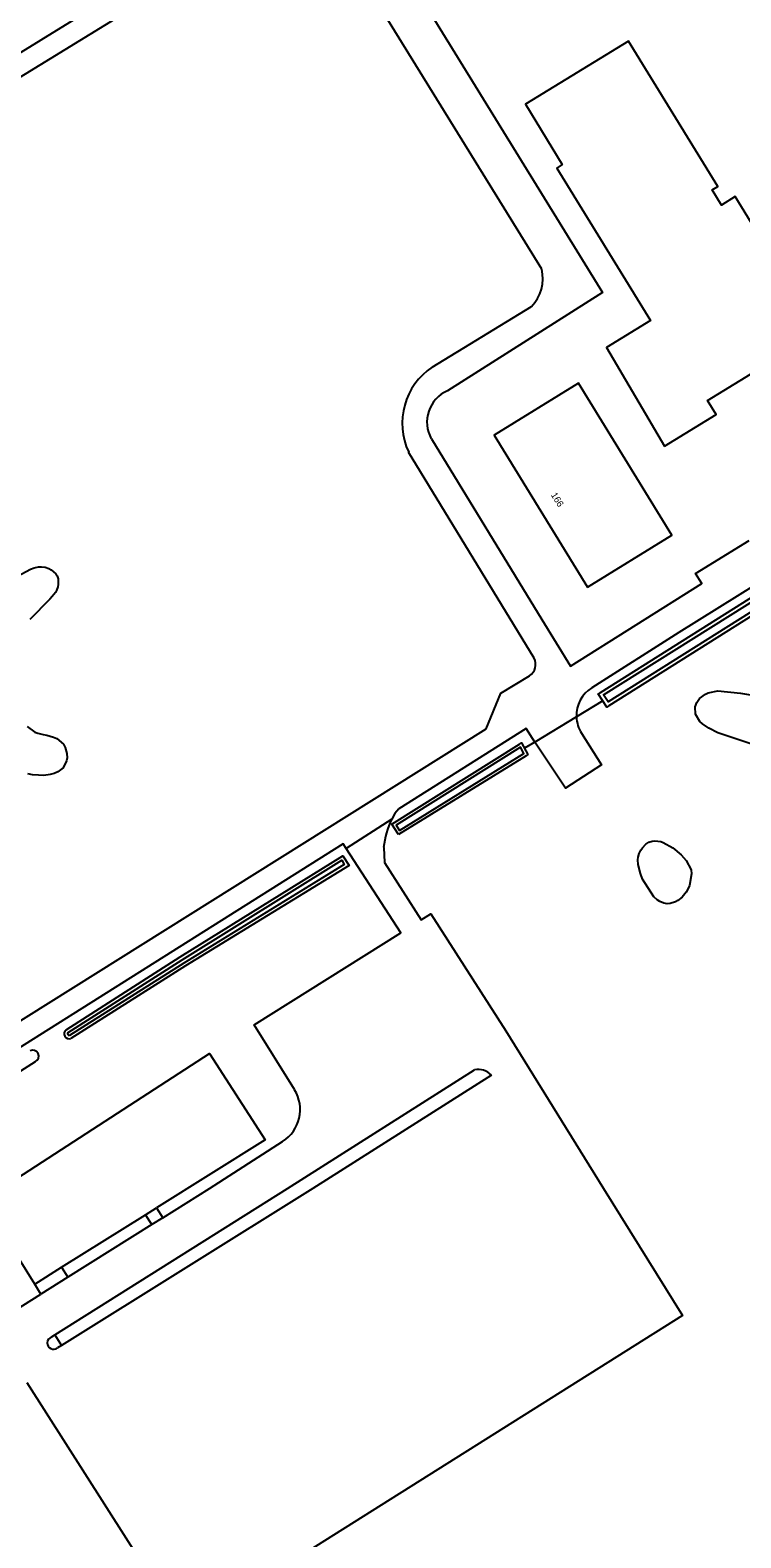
# Model space of a CAD drawing. Extents: x 156061 to 157804, y 383451 to 385640.
# Drawn here: x 157382.9 to 157488.8, y 384198 to 384422.5 of the extents above; entities that cross this region are included whole.
import ezdxf

# ---------------------------------------------------------------- set-up
doc = ezdxf.new("R2010")
doc.units = 0
for name, color, linetype in [('IMGEO_Duiker', 7, 'Continuous'), ('IMGEO_Groenvoorziening', 7, 'Continuous'), ('IMGEO_Pand', 7, 'Continuous'), ('IMGEO_Pand_nummerreeks', 7, 'Continuous'), ('IMGEO_Parkeervlak_open', 7, 'Continuous'), ('IMGEO_Rijbaan_lokaal_open', 7, 'Continuous'), ('IMGEO_Verkeerseiland_gesloten', 7, 'Continuous'), ('IMGEO_Voetpad_gesloten', 7, 'Continuous'), ('IMGEO_Voetpad_open', 7, 'Continuous'), ('IMGEO_Waterloop', 7, 'Continuous')]:
    doc.layers.add(name, color=color, linetype=linetype)

msp = doc.modelspace()

# ---------------------------------------------------------------- linework, layer by layer
at = {"layer": 'IMGEO_Duiker'}
msp.add_lwpolyline([(157468.24, 384322.62), (157464.32, 384320.24), (157458.11, 384316.49), (157456.56, 384315.56)], dxfattribs=at)
at = {"layer": 'IMGEO_Groenvoorziening'}
for points in [[(157500, 384341.28), (157469.14, 384321.89), (157468.85, 384321.71), (157467.54, 384323.67), (157467.87, 384323.89), (157500, 384344.09), (157567.48, 384386.23), (157568.22, 384386.06), (157568.84, 384385.18), (157568.87, 384384.42), (157500, 384341.28)], [(157375.35, 384338.18), (157382.95, 384342.26), (157383.48, 384342.45), (157384.14, 384342.61), (157384.56, 384342.61), (157385.11, 384342.52), (157385.65, 384342.33), (157386.01, 384342.15), (157386.7, 384341.57), (157386.9, 384341.26), (157387.05, 384340.81), (157387.06, 384339.96), (157387, 384339.62), (157386.82, 384339.09), (157386.64, 384338.76), (157386.19, 384338.19), (157385.8, 384337.79), (157382.85, 384334.74)], [(157490.88, 384316.01), (157485.38, 384317.89), (157484.06, 384318.55), (157483.07, 384319.2), (157482.68, 384319.57), (157482.05, 384320.66), (157482.02, 384321.74), (157482.26, 384322.38), (157482.67, 384322.96), (157483.52, 384323.61), (157483.93, 384323.81), (157485.4, 384324.14), (157488.74, 384323.78), (157491.37, 384323.35)], [(157382.43, 384318.82), (157383.6, 384317.96), (157384.05, 384317.8), (157384.83, 384317.64), (157385.39, 384317.53), (157386.37, 384317.24), (157386.87, 384317.01), (157387.84, 384316.18), (157388.12, 384315.7), (157388.37, 384314.77), (157388.38, 384314.13), (157388.32, 384313.7), (157387.82, 384312.67), (157387, 384312.04), (157386.48, 384311.81), (157385.89, 384311.64), (157384.92, 384311.52), (157384.12, 384311.54), (157383.24, 384311.63), (157382.53, 384311.74)], [(157437.78, 384302.72), (157436.8, 384304.27), (157455.82, 384316.16), (157456.1, 384316.36), (157457.08, 384314.64), (157456.81, 384314.44), (157437.78, 384302.72)], [(157481.14, 384295.14), (157480.93, 384294.58), (157480.66, 384294.12), (157480.04, 384293.41), (157479.44, 384292.91), (157479.08, 384292.7), (157478.26, 384292.43), (157477.82, 384292.42), (157477.32, 384292.52), (157476.72, 384292.74), (157476.32, 384292.98), (157475.83, 384293.45), (157474.17, 384296.05), (157473.83, 384296.9), (157473.49, 384298.28), (157473.45, 384298.94), (157473.51, 384299.37), (157473.67, 384299.89), (157473.92, 384300.4), (157474.15, 384300.73), (157474.63, 384301.27), (157475.12, 384301.59), (157475.6, 384301.74), (157476.01, 384301.78), (157476.86, 384301.66), (157477.22, 384301.54), (157478.66, 384300.73), (157479.92, 384299.68), (157480.64, 384298.87), (157481.39, 384297.46), (157481.45, 384296.86), (157481.14, 384295.14)], [(157405.26, 384284.49), (157429.48, 384299.57), (157430.41, 384298.1), (157406.06, 384283.15), (157388.95, 384272.33)], [(157388.24, 384273.63), (157405.26, 384284.49)]]:
    msp.add_lwpolyline(points, dxfattribs=at)
msp.add_arc((157388.71, 384273.04), 0.749, 128.4748, 288.337, dxfattribs=at)
at = {"layer": 'IMGEO_Pand'}
for points in [[(157477.44, 384360.55), (157485.12, 384365.26), (157483.83, 384367.34), (157500, 384377.25), (157500.4, 384377.5), (157500, 384378.16), (157487.98, 384397.76), (157485.91, 384396.48), (157484.54, 384398.72), (157485.36, 384399.22), (157472.06, 384420.9), (157456.69, 384411.48), (157462.2, 384402.49), (157461.4, 384401.99), (157475.33, 384379.26), (157468.81, 384375.27), (157477.44, 384360.55)], [(157465.94, 384339.56), (157478.53, 384347.29), (157464.63, 384369.94), (157452.04, 384362.21), (157465.94, 384339.56)]]:
    msp.add_lwpolyline(points, dxfattribs=at)
at = {"layer": 'IMGEO_Parkeervlak_open'}
for points in [[(157435.58, 384300.77), (157435.68, 384298.54), (157441.16, 384290.01), (157442.6, 384290.91), (157453.76, 384273.49), (157468.36, 384250), (157480.13, 384231.06), (157405.83, 384184.39), (157382.46, 384221.08)], [(157422.28, 384264.72), (157416.27, 384274.39), (157438.11, 384288.09), (157430, 384300.64)], [(157383.56, 384235.74), (157375.77, 384248.22), (157376.17, 384248.48), (157394.08, 384260.05), (157409.63, 384270.1), (157417.93, 384257.27), (157401.72, 384247.12)], [(157386.56, 384228.19), (157421.26, 384250), (157449.1, 384267.69)], [(157451.63, 384266.9), (157425, 384250), (157387.54, 384226.62)], [(157402.65, 384245.64), (157409.61, 384250), (157420.5, 384257)], [(157387.58, 384238.26), (157400.1, 384246.1)], [(157401.03, 384244.62), (157388.51, 384236.78)], [(157372.73, 384226.9), (157384.48, 384234.26)], [(157386.04, 384227.87), (157386.56, 384228.19)], [(157387.54, 384226.62), (157386.97, 384226.26)]]:
    msp.add_lwpolyline(points, dxfattribs=at)
for centre, radius, start, end in [((157447.84, 384299.56), 12.33, 153.6448, 174.3328), ((157449.64, 384264.96), 2.78, 44.2902, 101.2183), ((157417.51, 384261.75), 5.62, 302.1774, 31.8789), ((157386.38, 384226.99), 0.939, 111.1835, 309.2716)]:
    msp.add_arc(centre, radius, start, end, dxfattribs=at)
at = {"layer": 'IMGEO_Rijbaan_lokaal_open'}
for points in [[(157422.9, 384440.97), (157244.99, 384331.9), (157233.07, 384324.81), (157231.44, 384327.44), (157263.86, 384346.91), (157291.7, 384363.94), (157433.08, 384451.02), (157463.89, 384469.64), (157500, 384491.86), (157513.14, 384500), (157546.9, 384520.27), (157547.06, 384523.53), (157542.26, 384531.48), (157533.05, 384545.65), (157535.92, 384547.39), (157550.12, 384524.27), (157551.17, 384523.14), (157574.2, 384537.32)], [(157459.14, 384386.91), (157426.43, 384439.93), (157426.29, 384440.16)], [(157434.04, 384438.87), (157468.2, 384383.43), (157445.07, 384368.81)], [(157639.23, 384432.54), (157576.48, 384393.45), (157542.83, 384372.24), (157500, 384345.51), (157479.57, 384332.82), (157466.6, 384324.58)], [(157442.82, 384372.34), (157457.62, 384381.36)], [(157442.68, 384361.66), (157459.13, 384334.77), (157463.42, 384327.8), (157482.98, 384340.1), (157482.05, 384341.61), (157490.03, 384346.53)], [(157457.99, 384328.99), (157439.3, 384359.67)], [(157430, 384300.64), (157429.54, 384301.35), (157347.95, 384250), (157322.66, 384234.08), (157320.89, 384236.78), (157341.5, 384250), (157450.86, 384318.47), (157453.06, 384323.75), (157457.3, 384326.36)], [(157465.07, 384317.8), (157468.04, 384313.11), (157462.66, 384309.61), (157458.11, 384316.49), (157456.79, 384318.5), (157437.84, 384306.57), (157437.24, 384305.85), (157436.8, 384305.03)], [(157436.8, 384305.03), (157430, 384300.64)]]:
    msp.add_lwpolyline(points, dxfattribs=at)
for centre, radius, start, end in [((157453.3, 384385.53), 6, 316.0189, 13.3207), ((157448.38, 384363.97), 10.04, 123.5766, 205.3383), ((157447.14, 384364.15), 5.11, 113.9447, 209.1133), ((157456.24, 384328.05), 1.99, 302.1109, 28.211), ((157469.24, 384320.42), 4.93, 122.4518, 181.9995), ((157469.25, 384320.42), 4.94, 182.0776, 212.1015)]:
    msp.add_arc(centre, radius, start, end, dxfattribs=at)
at = {"layer": 'IMGEO_Verkeerseiland_gesloten'}
msp.add_lwpolyline([(157386.56, 384228.19), (157387.54, 384226.62)], dxfattribs=at)
at = {"layer": 'IMGEO_Voetpad_gesloten'}
for points in [[(157383.56, 384235.74), (157387.58, 384238.26)], [(157387.58, 384238.26), (157388.51, 384236.78)], [(157384.48, 384234.26), (157383.56, 384235.74)], [(157388.51, 384236.78), (157384.48, 384234.26)]]:
    msp.add_lwpolyline(points, dxfattribs=at)
at = {"layer": 'IMGEO_Voetpad_open'}
for points in [[(157400.1, 384246.1), (157401.72, 384247.12)], [(157401.03, 384244.62), (157400.1, 384246.1)], [(157401.72, 384247.12), (157402.65, 384245.64)], [(157402.65, 384245.64), (157401.03, 384244.62)]]:
    msp.add_lwpolyline(points, dxfattribs=at)
at = {"layer": 'IMGEO_Waterloop'}
for points in [[(157567.37, 384385.48), (157567.83, 384385.42), (157568.11, 384385), (157568.11, 384384.62), (157499.69, 384341.77), (157469.02, 384322.5), (157468.35, 384323.51), (157500.31, 384343.59), (157567.37, 384385.48)], [(157437.93, 384303.34), (157456.48, 384314.78), (157455.95, 384315.71), (157437.43, 384304.12), (157437.93, 384303.34)], [(157388.54, 384273.22), (157405.52, 384284.07), (157429.33, 384298.88), (157429.71, 384298.26), (157405.79, 384283.58), (157388.74, 384272.79)], [(157325.32, 384232.04), (157353.95, 384250), (157383.67, 384268.93)]]:
    msp.add_lwpolyline(points, dxfattribs=at)
for centre, radius, start, end in [((157388.71, 384273.04), 0.247, 132.4751, 278.1595), ((157383.27, 384269.72), 0.888, 296.1463, 116.0599)]:
    msp.add_arc(centre, radius, start, end, dxfattribs=at)

# ---------------------------------------------------------------- texts
at = {"layer": 'IMGEO_Pand_nummerreeks'}
msp.add_text('166', height=1, rotation=301.5461, dxfattribs=at).set_placement((157460.46, 384353.3))

doc.saveas('drawing.dxf')
